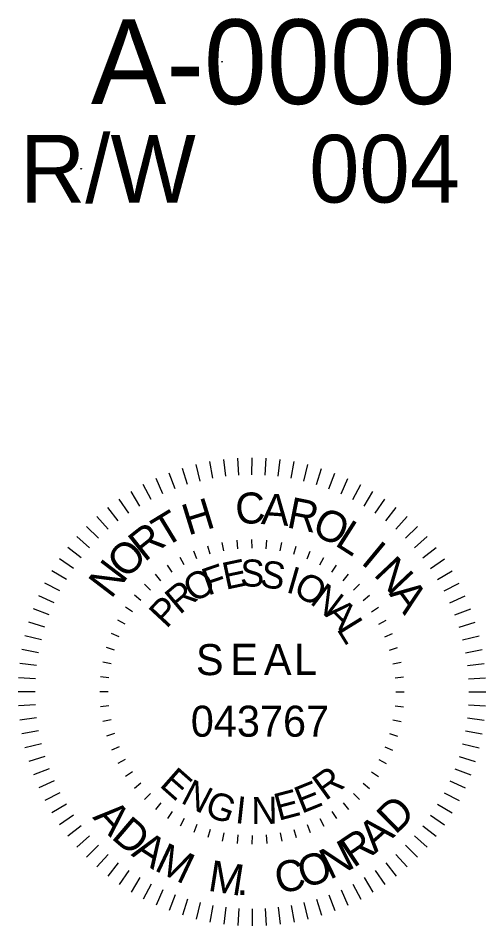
# Model space of a CAD drawing. Extents: x 24 to 1886, y 15 to 1115.
# Drawn here: x 1777.3 to 1860.3, y 932.5 to 1093.3 of the extents above; entities that cross this region are included whole.
import ezdxf

# ---------------------------------------------------------------- set-up
doc = ezdxf.new("R2010")
doc.units = 0
doc.layers.add('Sheet PE Seal CELL', color=7, linetype='Continuous')
doc.layers.add('Sheet_Title_Block_Text', color=7, linetype='Continuous')

msp = doc.modelspace()

# ---------------------------------------------------------------- linework, layer by layer
at = {"layer": 'Sheet PE Seal CELL'}
for p, q in [((1814.18, 1012.13), (1813.82, 1015.11)), ((1816.49, 1012.34), (1816.31, 1015.33)), ((1818.81, 1012.41), (1818.82, 1015.41)), ((1821.14, 1012.34), (1821.32, 1015.33)), ((1823.45, 1012.13), (1823.82, 1015.11)), ((1807.37, 1010.67), (1806.48, 1013.53)), ((1809.61, 1011.29), (1808.89, 1014.2)), ((1811.88, 1011.78), (1811.34, 1014.73)), ((1825.75, 1011.78), (1826.29, 1014.73)), ((1828.02, 1011.29), (1828.74, 1014.2)), ((1830.26, 1010.67), (1831.16, 1013.53)), ((1805.17, 1009.91), (1804.11, 1012.71)), ((1832.46, 1009.91), (1833.52, 1012.71)), ((1800.94, 1008), (1799.54, 1010.66)), ((1803.02, 1009.02), (1801.79, 1011.76)), ((1834.61, 1009.02), (1835.84, 1011.76)), ((1836.69, 1008), (1838.09, 1010.66)), ((1798.91, 1006.86), (1797.36, 1009.43)), ((1838.72, 1006.86), (1840.27, 1009.43)), ((1796.96, 1005.6), (1795.25, 1008.07)), ((1840.67, 1005.6), (1842.38, 1008.07)), ((1795.09, 1004.22), (1793.24, 1006.58)), ((1842.55, 1004.22), (1844.39, 1006.58)), ((1793.3, 1002.74), (1791.31, 1004.98)), ((1844.33, 1002.74), (1846.32, 1004.98)), ((1791.61, 1001.14), (1789.49, 1003.26)), ((1846.02, 1001.14), (1848.14, 1003.26)), ((1790.02, 999.45), (1787.77, 1001.44)), ((1816.32, 999.3), (1816.17, 1000.79)), ((1818.82, 999.42), (1818.81, 1000.92)), ((1821.31, 999.3), (1821.46, 1000.79)), ((1847.62, 999.45), (1849.86, 1001.44)), ((1788.53, 997.66), (1786.16, 999.51)), ((1811.42, 998.32), (1810.98, 999.75)), ((1813.84, 998.93), (1813.55, 1000.4)), ((1823.79, 998.93), (1824.08, 1000.4)), ((1826.21, 998.32), (1826.65, 999.75)), ((1849.1, 997.66), (1851.47, 999.51)), ((1787.15, 995.79), (1784.68, 997.49)), ((1806.8, 996.41), (1806.1, 997.73)), ((1809.06, 997.48), (1808.49, 998.87)), ((1828.57, 997.48), (1829.14, 998.86)), ((1830.83, 996.41), (1831.53, 997.73)), ((1850.48, 995.79), (1852.95, 997.49)), ((1804.66, 995.13), (1803.82, 996.37)), ((1832.97, 995.13), (1833.81, 996.37)), ((1785.89, 993.84), (1783.32, 995.39)), ((1802.65, 993.63), (1801.7, 994.79)), ((1834.98, 993.63), (1835.93, 994.79)), ((1851.74, 993.84), (1854.31, 995.39)), ((1784.74, 991.81), (1782.09, 993.21)), ((1800.8, 991.95), (1799.74, 993.01)), ((1836.84, 991.95), (1837.9, 993.01)), ((1852.89, 991.82), (1855.54, 993.21)), ((1783.73, 989.73), (1780.99, 990.95)), ((1799.12, 990.1), (1797.96, 991.05)), ((1838.52, 990.1), (1839.68, 991.05)), ((1853.9, 989.72), (1856.64, 990.95)), ((1782.84, 987.58), (1780.04, 988.64)), ((1797.63, 988.09), (1796.38, 988.93)), ((1840.01, 988.09), (1841.25, 988.92)), ((1854.79, 987.58), (1857.6, 988.64)), ((1782.08, 985.38), (1779.22, 986.27)), ((1796.34, 985.95), (1795.02, 986.65)), ((1841.29, 985.95), (1842.61, 986.65)), ((1855.55, 985.38), (1858.41, 986.27)), ((1781.46, 983.14), (1778.55, 983.86)), ((1795.27, 983.69), (1793.89, 984.26)), ((1842.36, 983.69), (1843.75, 984.26)), ((1856.17, 983.14), (1859.09, 983.86)), ((1780.97, 980.87), (1778.02, 981.41)), ((1794.43, 981.33), (1792.99, 981.76)), ((1843.2, 981.33), (1844.64, 981.76)), ((1856.66, 980.87), (1859.61, 981.41)), ((1780.62, 978.57), (1777.64, 978.93)), ((1793.82, 978.91), (1792.35, 979.2)), ((1843.81, 978.91), (1845.28, 979.2)), ((1857.01, 978.57), (1859.99, 978.93)), ((1793.45, 976.43), (1791.96, 976.58)), ((1844.18, 976.43), (1845.67, 976.58)), ((1780.41, 976.26), (1777.42, 976.44)), ((1857.22, 976.26), (1860.22, 976.44)), ((1780.34, 973.93), (1777.34, 973.93)), ((1793.33, 973.93), (1791.83, 973.93)), ((1844.3, 973.93), (1845.8, 973.93)), ((1857.29, 973.93), (1860.29, 973.93)), ((1780.41, 971.61), (1777.42, 971.43)), ((1793.45, 971.44), (1791.96, 971.29)), ((1844.18, 971.44), (1845.67, 971.29)), ((1857.22, 971.61), (1860.22, 971.43)), ((1780.62, 969.3), (1777.64, 968.93)), ((1793.82, 968.96), (1792.35, 968.67)), ((1843.81, 968.96), (1845.28, 968.67)), ((1857.01, 969.3), (1859.99, 968.93)), ((1780.97, 967), (1778.02, 966.46)), ((1856.66, 967), (1859.61, 966.46)), ((1794.43, 966.53), (1792.99, 966.1)), ((1843.2, 966.53), (1844.64, 966.1)), ((1781.46, 964.73), (1778.54, 964.01)), ((1795.27, 964.18), (1793.89, 963.61)), ((1842.36, 964.18), (1843.75, 963.61)), ((1856.17, 964.73), (1859.09, 964.01)), ((1782.08, 962.49), (1779.22, 961.6)), ((1855.55, 962.48), (1858.41, 961.6)), ((1796.34, 961.92), (1795.02, 961.21)), ((1841.29, 961.92), (1842.61, 961.21)), ((1782.84, 960.29), (1780.04, 959.23)), ((1797.63, 959.78), (1796.38, 958.94)), ((1840.01, 959.78), (1841.25, 958.94)), ((1854.79, 960.29), (1857.6, 959.23)), ((1783.73, 958.14), (1780.99, 956.91)), ((1799.12, 957.77), (1797.96, 956.81)), ((1838.52, 957.77), (1839.68, 956.81)), ((1853.9, 958.14), (1856.64, 956.91)), ((1784.75, 956.05), (1782.09, 954.66)), ((1800.8, 955.91), (1799.74, 954.85)), ((1836.84, 955.91), (1837.9, 954.85)), ((1852.89, 956.05), (1855.54, 954.66)), ((1785.89, 954.03), (1783.32, 952.48)), ((1802.65, 954.23), (1801.7, 953.07)), ((1834.98, 954.23), (1835.93, 953.07)), ((1851.74, 954.03), (1854.31, 952.48)), ((1804.66, 952.74), (1803.82, 951.5)), ((1832.97, 952.74), (1833.81, 951.5)), ((1787.15, 952.08), (1784.68, 950.37)), ((1806.8, 951.46), (1806.1, 950.14)), ((1830.83, 951.46), (1831.54, 950.14)), ((1850.48, 952.08), (1852.95, 950.37)), ((1788.53, 950.2), (1786.17, 948.36)), ((1809.06, 950.39), (1808.49, 949)), ((1811.42, 949.54), (1810.98, 948.11)), ((1826.21, 949.54), (1826.65, 948.11)), ((1828.57, 950.39), (1829.14, 949)), ((1849.1, 950.2), (1851.47, 948.36)), ((1790.02, 948.42), (1787.77, 946.43)), ((1813.84, 948.94), (1813.55, 947.47)), ((1816.32, 948.57), (1816.17, 947.08)), ((1818.82, 948.45), (1818.81, 946.95)), ((1821.31, 948.57), (1821.46, 947.08)), ((1823.79, 948.94), (1824.08, 947.47)), ((1847.62, 948.42), (1849.86, 946.43)), ((1791.61, 946.73), (1789.49, 944.61)), ((1846.02, 946.73), (1848.14, 944.61)), ((1793.3, 945.13), (1791.31, 942.89)), ((1844.33, 945.13), (1846.32, 942.89)), ((1795.09, 943.65), (1793.24, 941.28)), ((1842.55, 943.65), (1844.39, 941.28)), ((1796.96, 942.27), (1795.25, 939.8)), ((1840.67, 942.27), (1842.38, 939.8)), ((1798.91, 941.01), (1797.36, 938.44)), ((1800.94, 939.86), (1799.54, 937.21)), ((1836.69, 939.86), (1838.09, 937.21)), ((1838.72, 941.01), (1840.27, 938.44)), ((1803.02, 938.85), (1801.79, 936.11)), ((1805.17, 937.96), (1804.11, 935.15)), ((1832.46, 937.96), (1833.52, 935.15)), ((1834.61, 938.85), (1835.84, 936.11)), ((1807.37, 937.2), (1806.48, 934.33)), ((1809.61, 936.57), (1808.89, 933.66)), ((1828.02, 936.57), (1828.74, 933.66)), ((1830.26, 937.2), (1831.16, 934.33)), ((1811.88, 936.09), (1811.34, 933.14)), ((1814.18, 935.74), (1813.82, 932.76)), ((1816.49, 935.53), (1816.31, 932.53)), ((1818.82, 935.46), (1818.82, 932.46)), ((1821.14, 935.53), (1821.32, 932.53)), ((1823.45, 935.74), (1823.82, 932.76)), ((1825.75, 936.09), (1826.29, 933.14))]:
    msp.add_line(p, q, dxfattribs=at)
at = {"layer": 'Sheet_Title_Block_Text'}
for centre in [(1813.51, 1085.6), (1788.51, 1066.64), (1838.51, 1066.64)]:
    msp.add_circle(centre, 0.06, dxfattribs=at)

# ---------------------------------------------------------------- texts
at = {"layer": 'Sheet PE Seal CELL'}
for s, height, rotation, p in [('C', 5.5, 2.964, (1815.99, 1003.61)), ('A', 5.5, 355.8747, (1820.35, 1003.68)), ('H', 5.5, 17.1424, (1807.48, 1001.6)), ('R', 5.5, 348.7855, (1824.8, 1003.11)), ('T', 5.5, 31.3209, (1803.3, 999.36)), ('O', 5.5, 334.607, (1829.17, 1001.99)), ('L', 5.5, 327.5178, (1833.32, 1000)), ('R', 5.5, 38.4101, (1799.75, 996.83)), ('O', 5.5, 45.4993, (1796.5, 993.72)), ('I', 5.5, 320.4286, (1837.94, 996.76)), ('E', 4.8, 11.9657, (1814.14, 992)), ('S', 4.8, 357.9015, (1816.65, 992.66)), ('N', 5.5, 313.3394, (1840.22, 994.65)), ('N', 5.5, 52.5886, (1793.82, 990.28)), ('F', 4.8, 18.9979, (1810.98, 990.95)), ('S', 4.8, 350.8694, (1820.06, 992.61)), ('I', 4.8, 343.8373, (1824.67, 991.64)), ('O', 4.8, 33.0621, (1808.62, 989.54)), ('O', 4.8, 329.773, (1825.88, 991.39)), ('R', 4.8, 40.0942, (1805.98, 987.49)), ('N', 4.8, 322.7409, (1828.91, 989.67)), ('A', 5.5, 306.2501, (1843.01, 991.3)), ('P', 4.8, 47.1263, (1803.65, 985)), ('A', 4.8, 315.7088, (1831.52, 987.58)), ('L', 4.8, 301.6445, (1833.72, 985.08)), ('E', 4.8, 318.5439, (1802.23, 957.28)), ('R', 4.8, 35.8972, (1831.84, 954.52)), ('N', 4.8, 332.6082, (1805.99, 954.36)), ('E', 4.8, 21.833, (1827.61, 952.29)), ('G', 4.8, 339.6403, (1810.19, 952.13)), ('E', 4.8, 14.8009, (1823.5, 951.05)), ('I', 4.8, 353.7045, (1815.7, 950.7)), ('N', 4.8, 0.7366, (1818.73, 950.49)), ('D', 5.5, 44.5101, (1844.27, 948.49)), ('A', 5.5, 312.6603, (1790.43, 951.63)), ('D', 5.5, 319.5201, (1793.68, 948.05)), ('A', 5.5, 41.3416, (1840.7, 945.25)), ('R', 5.5, 33.8807, (1836.81, 942.64)), ('A', 5.5, 326.9811, (1797.24, 945.01)), ('N', 5.5, 26.4198, (1832.61, 940.57)), ('M', 5.5, 334.6907, (1801.29, 942.37)), ('C', 5.5, 11.2492, (1823.44, 938.12)), ('O', 5.5, 18.7101, (1828.04, 939.02)), ('M', 5.5, 351.0425, (1810.84, 938.71)), ('.', 5.5, 359.4983, (1816.08, 937.92))]:
    msp.add_text(s, height=height, rotation=rotation, dxfattribs=at).set_placement(p)
for s, height, p in [('S', 5.5, (1808.87, 976.89)), ('E', 5.5, (1814.96, 976.94)), ('A', 5.5, (1820.93, 976.92)), ('L', 5.5, (1826.25, 976.94)), ('043767', 5.497, (1807.96, 965.98))]:
    msp.add_text(s, height=height, dxfattribs=at).set_placement(p)
at = {"layer": 'Sheet_Title_Block_Text'}
for s, height, p in [('A-0000', 15, (1790.24, 1078.1)), ('R/W', 12, (1777.66, 1060.64)), ('004', 12, (1828.95, 1060.64))]:
    msp.add_text(s, height=height, dxfattribs=at).set_placement(p)

doc.saveas('drawing.dxf')
